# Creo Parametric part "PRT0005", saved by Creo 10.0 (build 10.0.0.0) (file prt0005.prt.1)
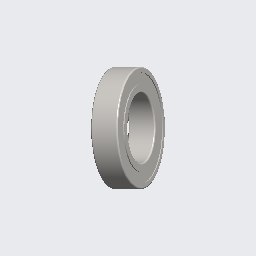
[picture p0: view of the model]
Units: millimeter Newton Second (mmNs); MM, TONNE, SECS

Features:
  1. coordinate system "KUGELLAGER"
  2. imported feature "Import-ke ID 4"

Other named items: NOTE_0

Notes: SS-61801-ZZ-MAE

Surfaces: 16 torus, 12 cylinder, 6 plane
